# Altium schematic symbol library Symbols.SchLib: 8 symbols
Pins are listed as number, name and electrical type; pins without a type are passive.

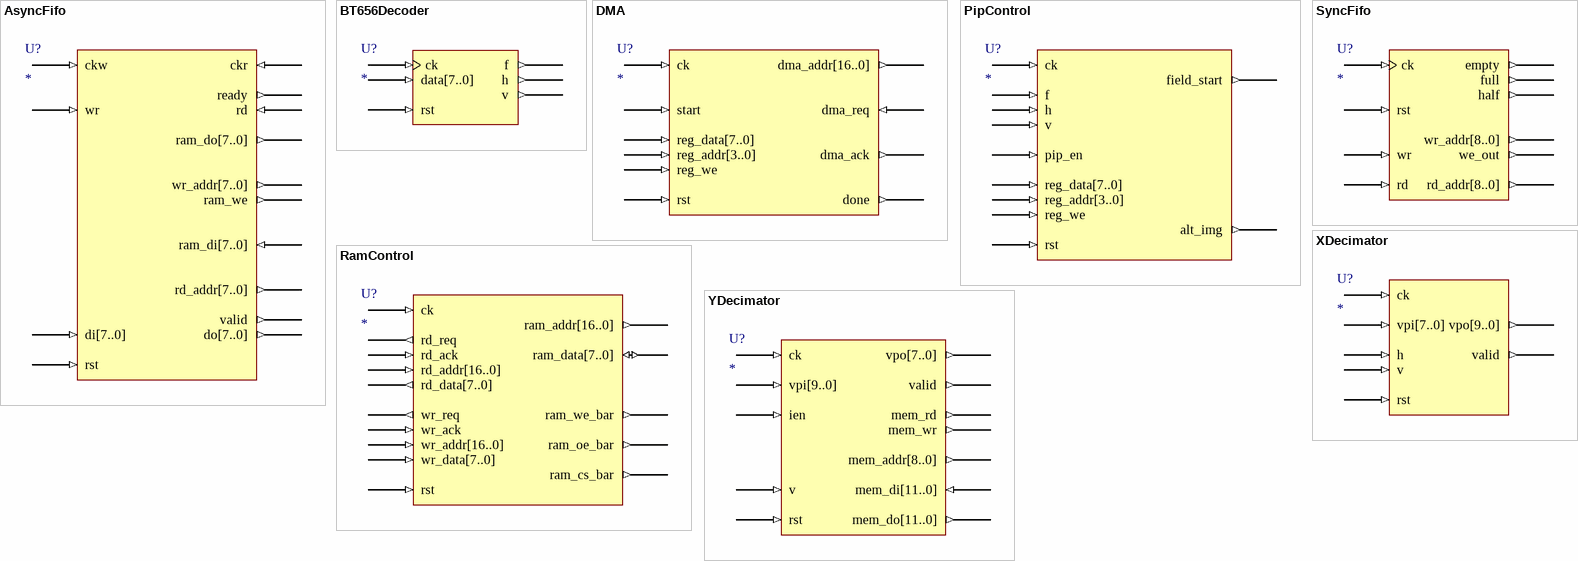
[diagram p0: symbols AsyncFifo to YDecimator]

## AsyncFifo
designator U?
pins: ckr (in), ckw (in), di[7..0] (in), do[7..0] (out), ram_di[7..0] (in), ram_do[7..0] (out), ram_we (out), rd (in), rd_addr[7..0] (out), ready (out), rst (in), valid (out), wr (in), wr_addr[7..0] (out)

## BT656Decoder
designator U?
pins: ck (in), data[7..0] (in), f (out), h (out), rst (in), v (out)

## DMA
designator U?
pins: ck (in), dma_ack (out), dma_addr[16..0] (out), dma_req (in), done (out), reg_addr[3..0] (in), reg_data[7..0] (in), reg_we (in), rst (in), start (in)

## PipControl
designator U?
pins: alt_img (out), ck (in), f (in), field_start (out), h (in), pip_en (in), reg_addr[3..0] (in), reg_data[7..0] (in), reg_we (in), rst (in), v (in)

## RamControl
designator U?
pins: ck (in), ram_addr[16..0] (out), ram_cs_bar (out), ram_data[7..0] (io), ram_oe_bar (out), ram_we_bar (out), rd_ack (in), rd_addr[16..0] (in), rd_data[7..0] (out), rd_req (out), rst (in), wr_ack (in), wr_addr[16..0] (in), wr_data[7..0] (in), wr_req (out)

## SyncFifo
designator U?
pins: ck (in), empty (out), full (out), half (out), rd (in), rd_addr[8..0] (out), rst (in), we_out (out), wr (in), wr_addr[8..0] (out)

## XDecimator
designator U?
pins: ck (in), h (in), rst (in), v (in), valid (out), vpi[7..0] (in), vpo[9..0] (out)

## YDecimator
designator U?
pins: ck (in), ien (in), mem_addr[8..0] (out), mem_di[11..0] (in), mem_do[11..0] (out), mem_rd (out), mem_wr (out), rst (in), v (in), valid (out), vpi[9..0] (in), vpo[7..0] (out)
